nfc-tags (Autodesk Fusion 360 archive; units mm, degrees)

design "NFC Tags" references "NFC Tag Rectangle", "NFC Tag Square", "NFC Tag Teardrop"
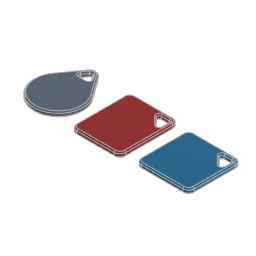
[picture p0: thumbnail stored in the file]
component_insert "Component Insert1"
component_insert "Component Insert2"
component_insert "Component Insert3"

design "NFC Tag Teardrop"
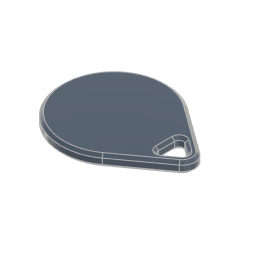
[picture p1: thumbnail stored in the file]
parameter "KeychainThickness" = 3.2
parameter "NFCTagDiameter" = 25
parameter "NFCTagClearance" = 0.4
parameter "KeychainEyelitRadius" = 3.6
parameter "KeychainBorderSpacing" = 2.4
parameter "KeychainChamferLength" = 0.8
parameter "KeychainEyelitAngle" = 72
parameter "KeychainLength" = 38
parameter "ScrewSlitLength" = 15
parameter "ScrewSlitWidth" = 2
parameter "ScrewSlitDepth" = 1.2
parameter "ScrewDepthClearance" = 0.2
parameter "NFCTagDepth" = 2.6
parameter "NFCTagHeight" = 0.6
parameter "d136" = 9.4
sketch "Layout" plane through (0, 0, 0) normal (0, 0, 1) x axis (1, 0, 0)
  line L1 (25.5228, 0) -> (8.8179, 12.1368)
  line L2 (25.5228, 0) -> (8.8179, -12.1368)
  line L3 (25.5228, 0) -> (0, 0)
  line L4 (21.5141, 2.9125) -> (8.8179, 12.1368)
  line L5 (21.5141, -2.9125) -> (8.8179, -12.1368)
  line L6 (22.9981, 0) -> (15.0019, 0)
  line L7 (20.1034, -0.9708) -> (7.4072, -10.1952)
  line L8 (20.1034, 0.9708) -> (7.4072, 10.1952)
  line L9 (20.1034, 0.9708) -> (16.9073, 3.293)
  line L10 (20.1034, -0.9708) -> (16.9073, -3.293)
  line L11 (15.0019, 4.6773) -> (15.0019, -4.6773)
  line L12 (15.0019, -2.3222) -> (15.0019, 2.3222)
  circle C1 centre (0, 0) radius 15.0019
  arc A1 centre (19.3981, 0) radius 3.6 clockwise from (21.5141, 2.9125) to (21.5141, -2.9125)
  arc A2 centre (19.3981, 0) radius 1.2 clockwise from (20.1034, 0.9708) to (20.1034, -0.9708)
  arc A3 centre (16.2019, 2.3222) radius 1.2 clockwise from (15.0019, 2.3222) to (16.9073, 3.293)
  arc A4 centre (16.2019, -2.3222) radius 1.2 clockwise from (16.9073, -3.293) to (15.0019, -2.3222)
  circle C2 centre (17.3851, 0) radius 2.3832
  point P1 (0, 0)
  point P2 (0, 0)
  point P3 (8.8179, 12.1368)
  point P4 (8.8179, -12.1368)
  point P6 (0, 0)
  point P5 (25.5228, 0)
  point P10 (15.0019, 0)
  point P11 (22.9981, 0)
  point P12 (-15.0019, 0)
  point P19 (15.0019, -4.6773)
  point P20 (15.0019, 4.6773)
  point P16 (20.1034, 0.9708)
  point P18 (20.1034, 0.9708)
  point P27 (14.2079, 0)
  point P28 (0, 0)
  point P29 (17.3851, 0)
  coincident P1 P2
  coincident C1 P3
  tangent C1 L1
  coincident C1 P4
  tangent C1 L2
  coincident P1 P6
  horizontal L3
  coincident P5 L4
  coincident P5 L5
  tangent L4 A1
  tangent L5 A1
  coincident L3 P10
  coincident C1 P10
  midpoint A1 P11
  coincident C1 P12
  coincident L3 P12
  parallel L8 L9
  collinear L7 L10
  collinear L8 L9
  coincident L7 P19
  coincident L8 P20
  vertical L11
  tangent C1 L11
  vertical L12
  coincident P16 P18
  tangent L12 A3
  tangent L9 A3
  tangent L12 A4
  tangent L10 A4
  equal A3 A4
  coincident L3 P27
  collinear L11 L12
  coincident P1 P28
  coincident L6 P29
  tangent L9 C2
  tangent L12 C2
  dimension "d2" diameter C1 = 30.0038
  dimension "d4" radius A1 = 3.6 (= "KeychainEyelitRadius")
  dimension "d14" distance P11 P12 = 38 (= "KeychainLength")
  dimension "d34" radius A3 = 1.2 (= "KeychainEyelitRadius - KeychainBorderSpacing")
  dimension "d38" angle L1 L2 = 72 (= "KeychainEyelitAngle")
  dimension "d108" diameter C2 = 4.7664
  dimension "d137" distance = 4.5
  dimension "d138" distance = 7.5
  dimension "d139" distance = 0.6
  dimension "d140" distance = 0.6
  dimension "d142" distance = 5.4
  dimension "d143" distance = 6.6
  dimension "d144" distance = 6.8
  dimension "d145" distance = 1.4
  dimension "d146" distance = 5.2
  dimension "d147" radius = 2.5
  dimension "d150" distance = 1
  dimension "d151" radius = 2.5
  dimension "d90" distance = 1
  dimension "d92" distance = 0 (= "5.312E-06 mm")
  dimension "d93" distance = 1
  dimension "d94" distance = 1
extrude "Extrude1" new body sketch "Layout" profile of C1 L4 L5 A1 A2 L9 L10 L12 A3 A4 along normal blind 3.2 (= "KeychainThickness") bodies "nfc-tag-teardrop"
chamfer "Chamfer2" distance 0.8 (= "KeychainChamferLength") distance 0.8 (= "KeychainChamferLength")
sketch "NFC Tag" plane through (0, 0, 3.2) normal (0, 0, 1) x axis (-1, 0, 0)
  line L1 (-20.5737, -1.618) -> (-17.3775, -3.9402)
  line L2 (-17.3775, 3.9402) -> (-20.5737, 1.618)
  line L3 (-14.2019, -2.3222) -> (-14.2019, 2.3222)
  line L4 (-21.0439, 2.2652) -> (-8.3477, 11.4896)
  line L5 (-8.3477, -11.4896) -> (-21.0439, -2.2652)
  line L6 (1, -7.5) -> (-1, -7.5)
  line L7 (1, 7.5) -> (1, -7.5)
  line L8 (-1, 7.5) -> (1, 7.5)
  line L9 (-1, -7.5) -> (-1, 7.5)
  line L10 (1, 7.5) -> (-1, -7.5)
  line L11 (-1, 7.5) -> (1, -7.5)
  arc A1 centre (-16.2019, -2.3222) radius 2 clockwise from (-14.2019, -2.3222) to (-17.3775, -3.9402)
  arc A2 centre (-19.3981, 0) radius 2 clockwise from (-20.5737, -1.618) to (-20.5737, 1.618)
  arc A3 centre (-16.2019, 2.3222) radius 2 clockwise from (-17.3775, 3.9402) to (-14.2019, 2.3222)
  arc A4 centre (-19.3981, 0) radius 2.8 clockwise from (-21.0439, -2.2652) to (-21.0439, 2.2652)
  arc A5 centre (0, 0) radius 14.2019 clockwise from (-8.3477, 11.4896) to (-8.3477, -11.4896)
  circle C1 centre (0, 0) radius 12.7
  circle C2 centre (0, 0) radius 12.9
  circle C3 centre (0, 0) radius 14.2019
  point P22 (0, 0)
  point P16 (0, 0)
  point P18 (-1, -7.5)
  point P19 (1, -7.5)
  point P20 (1, 7.5)
  concentric A5 C1
  horizontal L6
  perpendicular L6 L7
  parallel L6 L8
  parallel L7 L9
  coincident L10 P22
  coincident L11 P22
  coincident P16 P22
  concentric C1 C3
  tangent L3 C3
  dimension "d109" diameter C1 = 25.4 (= "NFCTagDiameter + NFCTagClearance")
  dimension "d110" = 0.2
  dimension "d111" distance P18 P19 = 2 (= "ScrewSlitWidth")
  dimension "d112" distance P19 P20 = 15 (= "ScrewSlitLength")
  dimension "d113" distance C2 C3 = 1.3019
extrude "Extrude9" sketch "NFC Tag" profile of C1 C2 L6 L7 L8 L9 blind 2.6 (= "NFCTagDepth")
extrude "Extrude13" sketch "NFC Tag" profile of C1 C2 no distance stored
thread "Thread1"
extrude "Extrude11" sketch "NFC Tag" profile of C1 C2 L6 L7 L8 L9 to an object offset 0.2 (= "ScrewDepthClearance") bodies "nfc-tag-screw"
thread "Thread2"
extrude "Extrude12" sketch "NFC Tag" profile of L6 L7 L8 L9 blind 1.2 (= "ScrewSlitDepth")
chamfer "Chamfer3" distance 1.2 (= "ScrewSlitDepth")
named bodies: "nfc-tag-teardrop", "nfc-tag-screw"

design "NFC Tag Rectangle"
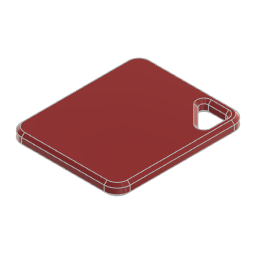
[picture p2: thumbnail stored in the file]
parameter "KeychainThickness" = 3.2
parameter "NFCTagDiameter" = 25
parameter "NFCTagClearance" = 0.4
parameter "KeychainRadius" = 3.6
parameter "KeychainEyelitRadius" = 1.2
parameter "KeychainEyelitSpacing" = 2.4
parameter "KeychainEyelitSize" = 7.2
parameter "KeychainHeight" = 36
parameter "KeychainWidth" = 30
parameter "KeychainChamferLength" = 0.8
parameter "ScrewSlitLength" = 15
parameter "ScrewSlitWidth" = 2
parameter "ScrewSlitDepth" = 1.2
parameter "ScrewDepthClearance" = 0.2
parameter "NFCTagDepth" = 2.6
parameter "NFCTagHeight" = 0.6
parameter "LayerHeight" = 0.2
parameter "NFCTagOffset" = 0.9 (= "( KeychainThickness - 0.8 mm - NFCTagThicknessAligned ) / 2")
parameter "NFCTagOffsetAligned" = 0.8 (= "NFCTagOffset - ( LayerHeight - ( NFCTagOffset % LayerHeight ) ) % LayerHeight")
parameter "LogoRecessDepth" = 0.8
parameter "LogoSymbolHeight" = 0.6
sketch "Layout" plane through (0, 0, 0) normal (0, 0, 1) x axis (1, 0, 0)
  line L1 (12, 18) -> (-18, 18)
  line L2 (12, -18) -> (12, 18)
  line L3 (-18, -18) -> (12, -18)
  line L4 (-18, 18) -> (-18, -18)
  line L5 (-18, -15.6) -> (-15.6, -15.6)
  line L6 (-15.6, -18) -> (-15.6, -15.6)
  line L7 (12, -15.6) -> (9.6, -15.6)
  line L8 (9.6, -18) -> (9.6, -15.6)
  line L9 (8.4, 18) -> (-14.4, 18)
  line L10 (12, -14.4) -> (12, 14.4)
  line L11 (-14.4, -18) -> (8.4, -18)
  line L12 (-18, 14.4) -> (-18, -14.4)
  line L13 (3.6, 15.6) -> (8.4, 15.6)
  line L14 (7.5515, 8.7515) -> (2.7515, 13.5515)
  line L15 (9.6, 14.4) -> (9.6, 9.6)
  line L16 (9.6, 15.6) -> (0.7029, 15.6)
  line L17 (9.6, 6.7029) -> (9.6, 15.6)
  line L18 (0.7029, 15.6) -> (9.6, 6.7029)
  line L19 (2.4, 15.6) -> (9.6, 15.6)
  line L20 (2.4, 8.4) -> (2.4, 15.6)
  line L21 (9.6, 8.4) -> (2.4, 8.4)
  line L22 (9.6, 15.6) -> (9.6, 8.4)
  line L23 (9.6, 6.7029) -> (9.6, 8.4)
  line L24 (9.6, 8.4) -> (2.4, 15.6)
  line L25 (2.4, 8.4) -> (9.6, 15.6)
  arc A1 centre (-14.4, 14.4) radius 3.6 clockwise from (-18, 14.4) to (-14.4, 18)
  arc A2 centre (-14.4, -14.4) radius 3.6 clockwise from (-14.4, -18) to (-18, -14.4)
  arc A3 centre (8.4, -14.4) radius 3.6 clockwise from (12, -14.4) to (8.4, -18)
  arc A4 centre (8.4, 14.4) radius 3.6 clockwise from (8.4, 18) to (12, 14.4)
  circle C1 centre (0, 0) radius 18
  arc A5 centre (3.6, 14.4) radius 1.2 clockwise from (2.7515, 13.5515) to (3.6, 15.6)
  arc A6 centre (8.4, 9.6) radius 1.2 clockwise from (9.6, 9.6) to (7.5515, 8.7515)
  arc A7 centre (8.4, 14.4) radius 1.2 clockwise from (8.4, 15.6) to (9.6, 14.4)
  circle C2 centre (6.9941, 12.9941) radius 2.6059
  arc A8 centre (-12, -12) radius 1
  arc A9 centre (-12, 12) radius 1
  arc A10 centre (12, -12) radius 1
  arc A11 centre (-1.0711, 12) radius 1
  arc A12 centre (12, -1.0711) radius 1
  point P8 (-18, -15.6)
  point P9 (-15.6, -18)
  point P10 (12, -15.6)
  point P11 (9.6, -18)
  point P32 (9.6, 15.6)
  point P1 (0, 0)
  point P24 (0, 0)
  point P40 (6.9941, 12.9941)
  point P2 (-18, 18)
  point P5 (-18, -18)
  point P39 (9.6, 8.4)
  point P6 (9.6, -15.6)
  horizontal L1
  vertical L2
  horizontal L3
  vertical L4
  coincident L4 P8
  perpendicular L4 L5
  coincident L3 P9
  perpendicular L3 L6
  coincident L2 P10
  perpendicular L2 L7
  coincident L3 P11
  perpendicular L3 L8
  equal L5 L6
  equal L5 L7
  horizontal L9
  vertical L10
  horizontal L11
  vertical L12
  tangent L9 A1
  tangent L12 A1
  tangent L11 A2
  tangent L12 A2
  tangent L10 A3
  tangent L11 A3
  tangent L9 A4
  tangent L10 A4
  equal A1 A4
  collinear L1 L9
  collinear L4 L12
  collinear L2 L10
  collinear L3 L11
  tangent L9 C1
  tangent L4 C1
  tangent L11 C1
  horizontal L13
  vertical L15
  tangent L14 A5
  tangent L13 A5
  tangent L14 A6
  tangent L15 A6
  equal A5 A6
  horizontal L16
  perpendicular L16 L17
  collinear L15 L17
  collinear L14 L18
  collinear L13 L16
  coincident L13 P32
  coincident L15 P32
  tangent L13 A7
  tangent L15 A7
  horizontal L19
  vertical L20
  horizontal L21
  vertical L22
  equal L20 L21
  tangent A6 L21
  equal A2 A3
  coincident P1 P24
  coincident L25 P40
  tangent L18 C2
  tangent L16 C2
  collinear L5 L7
  dimension "d44" distance P2 P5 = 36 (= "KeychainHeight")
  dimension "d47" radius A1 = 3.6 (= "KeychainRadius")
  dimension "d50" diameter C1 = 36
  dimension "d52" angle L13 L14 = 45
  dimension "d53" radius A5 = 1.2 (= "KeychainEyelitRadius")
  dimension "d65" distance P32 P39 = 7.2 (= "KeychainEyelitSize")
  dimension "d71" radius A7 = 1.2 (= "KeychainEyelitRadius")
  dimension "d80" distance P6 P10 = 2.4 (= "KeychainEyelitSpacing")
  dimension "d81" distance L2 L4 = 30 (= "KeychainWidth")
  dimension "d90" radius A2 = 3.6 (= "KeychainRadius")
  dimension "d127" diameter C2 = 5.2118
  dimension "d159" distance L2 L17 = 2.4 (= "KeychainEyelitSpacing")
  dimension "d166" distance L20 L22 = 7.2
  dimension "d167" distance L9 L16 = 2.4 (= "KeychainEyelitSpacing")
  dimension "d184" distance = 3 (= "KeychainEyelitSpacing")
  dimension "d185" radius = 1
  dimension "d186" radius = 1
  dimension "d187" distance = 3
extrude "Extrude6" new body sketch "Layout" profile of L9 L10 L11 L12 A1 A2 A3 A4 L13 L14 L15 A5 A6 A7 along normal blind 3.2 (= "KeychainThickness")
chamfer "Chamfer5" distance 0.8 (= "KeychainChamferLength") distance 0.8 (= "KeychainChamferLength")
sketch "NFC Tag" plane through (0, 0, 3.2) normal (0, 0, 1) x axis (1, 0, 0)
  line L1 (-3, -17.2) -> (-3, 17.2)
  line L2 (11.2, 14.4) -> (11.2, -14.4)
  line L3 (-14.4, 17.2) -> (8.4, 17.2)
  line L4 (-17.2, -14.4) -> (-17.2, 14.4)
  line L5 (8.4, -17.2) -> (-14.4, -17.2)
  line L6 (8.4, 16.4) -> (3.6, 16.4)
  line L7 (10.4, 9.6) -> (10.4, 14.4)
  line L8 (2.1858, 12.9858) -> (6.9858, 8.1858)
  line L9 (-4, 4.7) -> (-2, 4.7)
  line L10 (-4, -10.3) -> (-4, 4.7)
  line L11 (-2, -10.3) -> (-4, -10.3)
  line L12 (-2, 4.7) -> (-2, -10.3)
  line L13 (-2, -10.3) -> (-4, 4.7)
  line L14 (-2, 4.7) -> (-4, -10.3)
  line L15 (-18, 14.4) -> (-18, -14.4)
  line L16 (-14.4, -18) -> (8.4, -18)
  line L17 (12, -14.4) -> (12, 14.4)
  line L18 (-3, -17) -> (-3, -17.2)
  circle C1 centre (-3, -2.8) radius 12.7
  arc A1 centre (8.4, 14.4) radius 2.8 clockwise from (8.4, 17.2) to (11.2, 14.4)
  arc A2 centre (-14.4, 14.4) radius 2.8 clockwise from (-17.2, 14.4) to (-14.4, 17.2)
  arc A3 centre (-14.4, -14.4) radius 2.8 clockwise from (-14.4, -17.2) to (-17.2, -14.4)
  arc A4 centre (8.4, -14.4) radius 2.8 clockwise from (11.2, -14.4) to (8.4, -17.2)
  arc A5 centre (3.6, 14.4) radius 2 clockwise from (2.1858, 12.9858) to (3.6, 16.4)
  arc A6 centre (8.4, 14.4) radius 2 clockwise from (8.4, 16.4) to (10.4, 14.4)
  arc A7 centre (8.4, 9.6) radius 2 clockwise from (10.4, 9.6) to (6.9858, 8.1858)
  circle C2 centre (-3, -2.8) radius 12.9
  circle C3 centre (-3, -2.8) radius 14.2
  point P4 (-3, -17.2)
  point P3 (-3, 17.2)
  point P28 (-2, 4.7)
  point P32 (-2, 4.7)
  point P33 (-3, -2.8)
  point P2 (-3, -2.8)
  point P42 (-3, -2.8)
  point P43 (-3, -17)
  point P29 (-4, 4.7)
  point P30 (-4, -10.3)
  vertical L1
  midpoint P4 L5
  midpoint P3 L3
  perpendicular L9 L10
  perpendicular L10 L11
  perpendicular L9 L12
  coincident P28 P32
  midpoint L14 P33
  coincident P2 P33
  vertical L10
  coincident P2 L1
  coincident P33 P42
  tangent L2 C3
  coincident L1 P43
  coincident C3 P43
  dimension "d120" diameter C1 = 25.4 (= "NFCTagDiameter + NFCTagClearance")
  dimension "d223" = 0.2
  dimension "d224" diameter C2 = 25.8
  dimension "d231" distance P28 P29 = 2 (= "ScrewSlitWidth")
  dimension "d232" distance P29 P30 = 15 (= "ScrewSlitLength")
  dimension "d268" distance C2 C3 = 1.3
  dimension "d269" distance P4 P43 = 0.2
  dimension "d175" angle = 45
  dimension "d176" distance = 2.6667 (= "KeychainEyelitSize / 3")
extrude "Extrude11" sketch "NFC Tag" profile of C1 C2 L9 L10 L11 L12 blind 2.6 (= "NFCTagDepth")
extrude "Extrude20" sketch "NFC Tag" profile of C1 C2 no distance stored
thread "Thread1"
extrude "Extrude17" sketch "NFC Tag" profile of C1 C2 L9 L10 L11 L12 to an object offset 0.2 (= "ScrewDepthClearance") bodies "nfc-tag-screw"
thread "Thread2"
extrude "Extrude19" sketch "NFC Tag" profile of L9 L10 L11 L12 blind 1.2 (= "ScrewSlitDepth")
chamfer "Chamfer10" distance 1.2 (= "ScrewSlitDepth")
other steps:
step "Extrude15" sketch "Layout" ProfileOffset 0 AlongDistance -0.8 TaperAngle 0
step "Chamfer" Distance 0.8
step "Extrude16" AlongDistance 0.6 TaperAngle 0
step "Sketch" Linear Dimension-3 1 Linear Dimension-5 1 Linear Dimension-7 1 Linear Dimension-8 12 Linear Dimension-9 12 Radial Dimension-2 2 Linear Dimension-10 2.6 Linear Dimension-11 3.6 Linear Dimension-12 8.4 Linear Dimension-13 9.4 Linear Dimension-14 4.5 Linear Dimension-15 7.5 Linear Dimension-16 0.6 Linear Dimension-17 0.6 Linear Dimension-18 5.4 Linear Dimension-19 6.6 Linear Dimension-20 6.8 Linear Dimension-21 1.4 Linear Dimension-22 5.2 Radial Dimension-3 2.5 Linear Dimension-23 1 Radial Dimension-4 2.5 Angular Dimension-2 45 Linear Dimension-21 1.5 Linear Dimension-22 1.5 Linear Dimension-23 1 Linear Dimension-24 1
named bodies: "nfc-tag-rectangle", "nfc-tag-screw"

design "NFC Tag Square"
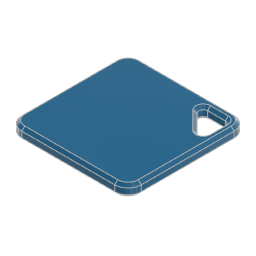
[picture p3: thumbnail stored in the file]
parameter "KeychainThickness" = 3.2
parameter "NFCTagDiameter" = 25
parameter "NFCTagClearance" = 0.4
parameter "KeychainRadius" = 3.6
parameter "KeychainEyelitRadius" = 1.2
parameter "KeychainEyelitSpacing" = 2.4
parameter "KeychainEyelitSize" = 7.2
parameter "KeychainHeight" = 32.4
parameter "KeychainWidth" = 32.4
parameter "KeychainChamferLength" = 0.8
parameter "ScrewSlitLength" = 15
parameter "ScrewSlithWidth" = 2
parameter "NFCTagDepth" = 2.6
parameter "NFCTagHeight" = 0.6
parameter "ScrewSlitDepth" = 1.2
parameter "ScrewDepthClearance" = 0.2
parameter "LayerHeight" = 0.2
parameter "NFCTagOffset" = 0.9 (= "( KeychainThickness - 0.8 mm - NFCTagThicknessAligned ) / 2")
parameter "NFCTagOffsetAligned" = 0.8 (= "NFCTagOffset - ( LayerHeight - ( NFCTagOffset % LayerHeight ) ) % LayerHeight")
parameter "LogoRecessDepth" = 0.8
parameter "LogoSymbolHeight" = 0.6
sketch "Layout" plane through (0, 0, 0) normal (0, 0, 1) x axis (1, 0, 0)
  line L1 (16.2, 16.2) -> (-16.2, 16.2)
  line L2 (16.2, -16.2) -> (16.2, 16.2)
  line L3 (-16.2, -16.2) -> (16.2, -16.2)
  line L4 (-16.2, 16.2) -> (-16.2, -16.2)
  line L5 (-16.2, -13.8) -> (-13.8, -13.8)
  line L6 (-13.8, -16.2) -> (-13.8, -13.8)
  line L7 (16.2, -13.8) -> (13.8, -13.8)
  line L8 (13.8, -16.2) -> (13.8, -13.8)
  line L9 (12.6, 16.2) -> (-12.6, 16.2)
  line L10 (16.2, -12.6) -> (16.2, 12.6)
  line L11 (-12.6, -16.2) -> (12.6, -16.2)
  line L12 (-16.2, 12.6) -> (-16.2, -12.6)
  line L13 (7.8, 13.8) -> (12.6, 13.8)
  line L14 (11.7515, 6.9515) -> (6.9515, 11.7515)
  line L15 (13.8, 12.6) -> (13.8, 7.8)
  line L16 (13.8, 13.8) -> (4.9029, 13.8)
  line L17 (13.8, 4.9029) -> (13.8, 13.8)
  line L18 (4.9029, 13.8) -> (13.8, 4.9029)
  line L19 (6.6, 13.8) -> (13.8, 13.8)
  line L20 (6.6, 6.6) -> (6.6, 13.8)
  line L21 (13.8, 6.6) -> (6.6, 6.6)
  line L22 (13.8, 13.8) -> (13.8, 6.6)
  line L23 (13.8, 4.9029) -> (13.8, 6.6)
  line L24 (13.8, 6.6) -> (6.6, 13.8)
  line L25 (6.6, 6.6) -> (13.8, 13.8)
  arc A1 centre (-12.6, 12.6) radius 3.6 clockwise from (-16.2, 12.6) to (-12.6, 16.2)
  arc A2 centre (-12.6, -12.6) radius 3.6 clockwise from (-12.6, -16.2) to (-16.2, -12.6)
  arc A3 centre (12.6, -12.6) radius 3.6 clockwise from (16.2, -12.6) to (12.6, -16.2)
  arc A4 centre (12.6, 12.6) radius 3.6 clockwise from (12.6, 16.2) to (16.2, 12.6)
  circle C1 centre (0, 0) radius 16.2
  arc A5 centre (7.8, 12.6) radius 1.2 clockwise from (6.9515, 11.7515) to (7.8, 13.8)
  arc A6 centre (12.6, 7.8) radius 1.2 clockwise from (13.8, 7.8) to (11.7515, 6.9515)
  arc A7 centre (12.6, 12.6) radius 1.2 clockwise from (12.6, 13.8) to (13.8, 12.6)
  circle C2 centre (11.1941, 11.1941) radius 2.6059
  point P8 (-16.2, -13.8)
  point P9 (-13.8, -16.2)
  point P10 (16.2, -13.8)
  point P11 (13.8, -16.2)
  point P32 (13.8, 13.8)
  point P1 (0, 0)
  point P24 (0, 0)
  point P40 (11.1941, 11.1941)
  point P2 (-16.2, 16.2)
  point P5 (-16.2, -16.2)
  point P39 (13.8, 6.6)
  point P6 (13.8, -13.8)
  horizontal L1
  vertical L2
  horizontal L3
  vertical L4
  coincident L4 P8
  perpendicular L4 L5
  coincident L3 P9
  perpendicular L3 L6
  coincident L2 P10
  perpendicular L2 L7
  coincident L3 P11
  perpendicular L3 L8
  equal L5 L6
  equal L5 L7
  horizontal L9
  vertical L10
  horizontal L11
  vertical L12
  tangent L9 A1
  tangent L12 A1
  tangent L11 A2
  tangent L12 A2
  tangent L10 A3
  tangent L11 A3
  tangent L9 A4
  tangent L10 A4
  equal A1 A4
  collinear L1 L9
  collinear L4 L12
  collinear L2 L10
  collinear L3 L11
  tangent L9 C1
  tangent L4 C1
  tangent L11 C1
  horizontal L13
  vertical L15
  tangent L14 A5
  tangent L13 A5
  tangent L14 A6
  tangent L15 A6
  equal A5 A6
  horizontal L16
  perpendicular L16 L17
  collinear L15 L17
  collinear L14 L18
  collinear L13 L16
  coincident L13 P32
  coincident L15 P32
  tangent L13 A7
  tangent L15 A7
  horizontal L19
  vertical L20
  horizontal L21
  vertical L22
  equal L20 L21
  tangent A6 L21
  equal A2 A3
  coincident P1 P24
  coincident L25 P40
  tangent L18 C2
  tangent L16 C2
  collinear L5 L7
  dimension "d44" distance P2 P5 = 32.4 (= "KeychainHeight")
  dimension "d47" radius A1 = 3.6 (= "KeychainRadius")
  dimension "d50" diameter C1 = 32.4
  dimension "d52" angle L13 L14 = 45
  dimension "d53" radius A5 = 1.2 (= "KeychainEyelitRadius")
  dimension "d65" distance P32 P39 = 7.2 (= "KeychainEyelitSize")
  dimension "d71" radius A7 = 1.2 (= "KeychainEyelitRadius")
  dimension "d80" distance P6 P10 = 2.4 (= "KeychainEyelitSpacing")
  dimension "d81" distance L2 L4 = 32.4 (= "KeychainWidth")
  dimension "d90" radius A2 = 3.6 (= "KeychainRadius")
  dimension "d127" diameter C2 = 5.2118
  dimension "d159" distance L2 L17 = 2.4 (= "KeychainEyelitSpacing")
  dimension "d166" distance L20 L22 = 7.2
  dimension "d167" distance L9 L16 = 2.4 (= "KeychainEyelitSpacing")
  dimension "d184" distance = 3 (= "KeychainEyelitSpacing")
  dimension "d185" radius = 1
  dimension "d186" radius = 1
  dimension "d187" distance = 3
  dimension "d188" ProfileOffset = 0
  dimension "d189" AlongDistance = -0.8
  dimension "d190" TaperAngle = 0
  dimension "d191" Distance = 0.8
  dimension "d214" AlongDistance = 0.6
  dimension "d215" TaperAngle = 0
extrude "Extrude6" new body sketch "Layout" profile of L9 L10 L11 L12 A1 A2 A3 A4 L13 L14 L15 A5 A6 A7 along normal blind 3.2 (= "KeychainThickness")
chamfer "Chamfer5" distance 0.8 (= "KeychainChamferLength") distance 0.8 (= "KeychainChamferLength")
sketch "NFC Tag" plane through (0, 0, 3.2) normal (0, 0, 1) x axis (1, 0, 0)
  line L1 (15.4, 0) -> (-15.4, 0)
  line L2 (0, -15.4) -> (0, 15.4)
  line L3 (15.4, 12.6) -> (15.4, -12.6)
  line L4 (-12.6, 15.4) -> (12.6, 15.4)
  line L5 (-15.4, -12.6) -> (-15.4, 12.6)
  line L6 (12.6, -15.4) -> (-12.6, -15.4)
  line L7 (12.6, 14.6) -> (7.8, 14.6)
  line L8 (14.6, 7.8) -> (14.6, 12.6)
  line L9 (6.3858, 11.1858) -> (11.1858, 6.3858)
  line L10 (-0.2323, -8.7323) -> (-2.2323, -8.7323)
  line L11 (-0.2323, 6.2677) -> (-0.2323, -8.7323)
  line L12 (-2.2323, 6.2677) -> (-0.2323, 6.2677)
  line L13 (-2.2323, -8.7323) -> (-2.2323, 6.2677)
  line L14 (-2.2323, 6.2677) -> (-0.2323, -8.7323)
  line L15 (-2.2323, -8.7323) -> (-0.2323, 6.2677)
  line L16 (-16.2, 12.6) -> (-16.2, -12.6)
  circle C1 centre (-1.2323, -1.2323) radius 12.7
  arc A1 centre (12.6, 12.6) radius 2.8 clockwise from (12.6, 15.4) to (15.4, 12.6)
  arc A2 centre (-12.6, 12.6) radius 2.8 clockwise from (-15.4, 12.6) to (-12.6, 15.4)
  arc A3 centre (-12.6, -12.6) radius 2.8 clockwise from (-12.6, -15.4) to (-15.4, -12.6)
  arc A4 centre (12.6, -12.6) radius 2.8 clockwise from (15.4, -12.6) to (12.6, -15.4)
  arc A5 centre (7.8, 12.6) radius 2 clockwise from (6.3858, 11.1858) to (7.8, 14.6)
  arc A6 centre (12.6, 12.6) radius 2 clockwise from (12.6, 14.6) to (14.6, 12.6)
  arc A7 centre (12.6, 7.8) radius 2 clockwise from (14.6, 7.8) to (11.1858, 6.3858)
  circle C2 centre (-1.2323, -1.2323) radius 12.9
  circle C3 centre (-1.2323, -1.2323) radius 14.1677
  circle C4 centre (-1.2323, -1.2323) radius 14.9677
  point P2 (-1.2323, -1.2323)
  point P3 (-1.2323, -1.2323)
  point P7 (0, -15.4)
  point P6 (0, 15.4)
  point P4 (-15.4, 0)
  point P5 (15.4, 0)
  point P31 (-2.2323, -8.7323)
  point P35 (-2.2323, -8.7323)
  point P36 (-1.2323, -1.2323)
  point P37 (-1.2323, -1.2323)
  point P38 (-1.2323, -1.2323)
  point P32 (-0.2323, -8.7323)
  point P33 (-0.2323, 6.2677)
  coincident P2 P3
  vertical L2
  midpoint P7 L6
  midpoint P6 L4
  midpoint P4 L5
  midpoint P5 L3
  perpendicular L10 L11
  perpendicular L11 L12
  perpendicular L10 L13
  coincident P31 P35
  midpoint L15 P36
  coincident P3 P36
  coincident P2 P37
  tangent L9 C3
  tangent L6 C3
  tangent L5 C3
  coincident P36 P38
  tangent C4 L16
  vertical L13
  dimension "d120" diameter C1 = 25.4 (= "NFCTagDiameter + NFCTagClearance")
  dimension "d223" = 0.2
  dimension "d224" diameter C2 = 25.8
  dimension "d231" distance P31 P32 = 2 (= "ScrewSlithWidth")
  dimension "d232" distance P32 P33 = 15 (= "ScrewSlitLength")
  dimension "d266" diameter C4 = 29.9354
  dimension "d267" distance C2 C3 = 1.2677
  dimension "d175" angle = 45
  dimension "d176" distance = 2.6667 (= "KeychainEyelitSize / 3")
extrude "Extrude11" sketch "NFC Tag" profile of C1 C2 L10 L11 L12 L13 blind 2.6 (= "NFCTagDepth")
extrude "Extrude20" sketch "NFC Tag" profile of C1 C2 no distance stored
thread "Thread1"
extrude "Extrude17" sketch "NFC Tag" profile of C1 C2 L10 L11 L12 L13 to an object offset 0.2 (= "ScrewDepthClearance") bodies "nfc-tag-screw"
thread "Thread2"
extrude "Extrude19" sketch "NFC Tag" profile of L10 L11 L12 L13 blind 1.2 (= "ScrewSlitDepth")
chamfer "Chamfer10" distance 1.2 (= "ScrewSlitDepth")
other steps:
step "Sketch" Linear Dimension-3 1 Linear Dimension-5 1 Linear Dimension-7 1 Linear Dimension-8 12 Linear Dimension-9 12 Radial Dimension-2 2 Linear Dimension-10 2.6 Linear Dimension-11 3.6 Linear Dimension-12 8.4 Linear Dimension-13 9.4 Linear Dimension-14 4.5 Linear Dimension-15 7.5 Linear Dimension-16 0.6 Linear Dimension-17 0.6 Linear Dimension-18 5.4 Linear Dimension-19 6.6 Linear Dimension-20 6.8 Linear Dimension-21 1.4 Linear Dimension-22 5.2 Radial Dimension-3 2.5 Linear Dimension-23 1 Radial Dimension-4 2.5 Angular Dimension-2 45 Linear Dimension-21 1.5 Linear Dimension-22 1.5 Linear Dimension-23 1 Linear Dimension-24 1
named bodies: "nfc-tag-square", "nfc-tag-screw"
